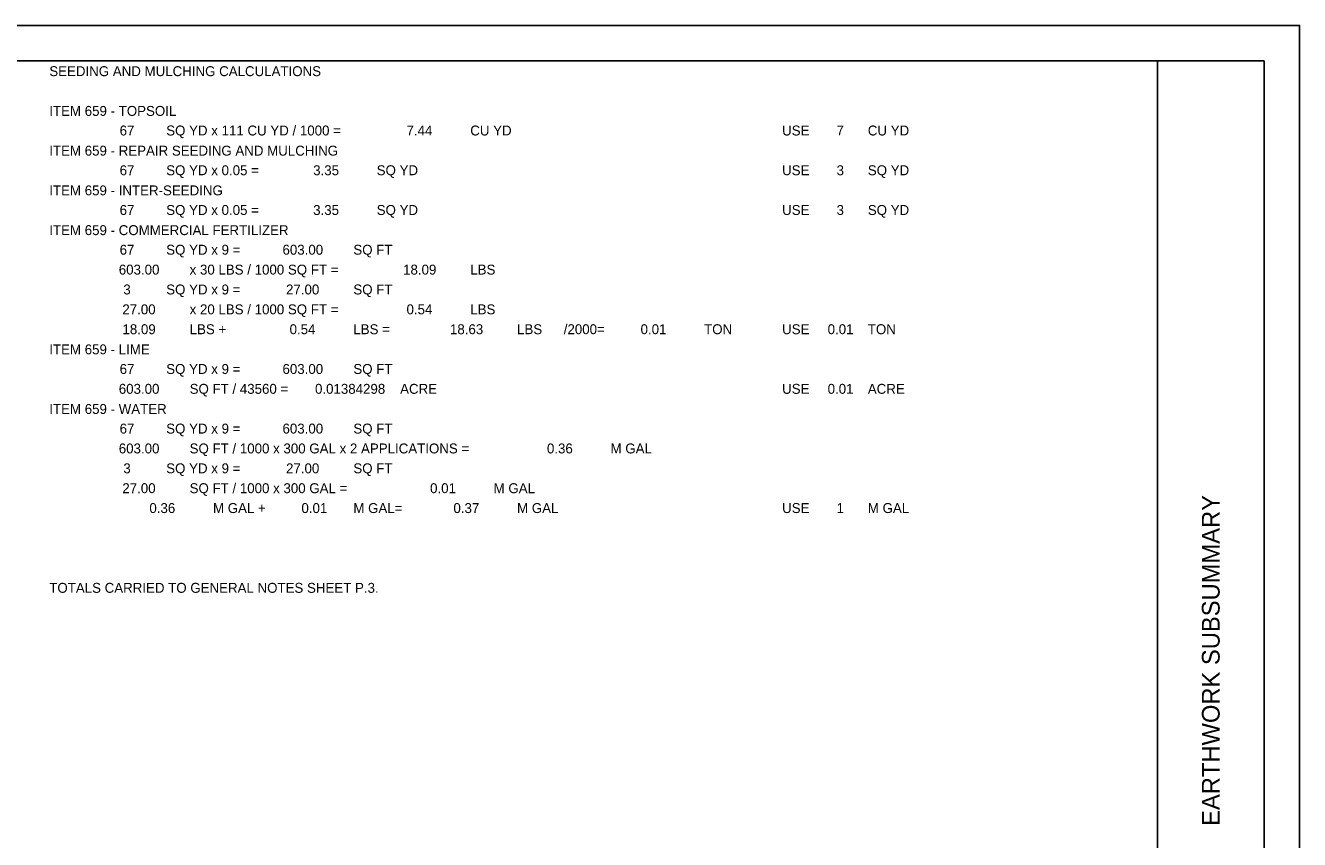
# Model space of a CAD drawing. Extents: x 0 to 34, y 0 to 22.
# Drawn here: x 16.05 to 34, y 10.53 to 22 of the extents above; entities that cross this region are included whole.
import ezdxf

# ---------------------------------------------------------------- set-up
doc = ezdxf.new("R2010")
doc.units = 0
for name, color, linetype in [('SH_Border', 7, 'Continuous'), ('SH_Cut_Line', 7, 'Continuous'), ('SH_Data', 7, 'Continuous'), ('SH_Text', 7, 'Continuous')]:
    doc.layers.add(name, color=color, linetype=linetype)

msp = doc.modelspace()

# ---------------------------------------------------------------- linework, layer by layer
at = {"layer": 'SH_Border'}
msp.add_line((32, 0.5), (32, 21.5), dxfattribs=at)
msp.add_lwpolyline([(1.5, 21.5), (33.5, 21.5), (33.5, 0.5), (1.5, 0.5)], close=True, dxfattribs=at)
at = {"layer": 'SH_Cut_Line'}
msp.add_lwpolyline([(0, 0), (34, 0), (34, 22), (0, 22)], close=True, dxfattribs=at)

# ---------------------------------------------------------------- texts
at = {"layer": 'SH_Data'}
msp.add_text('EARTHWORK SUBSUMMARY', height=0.25, rotation=90, dxfattribs=at).set_placement((32.875, 10.722))
at = {"layer": 'SH_Text'}
for s, p in [('SEEDING AND MULCHING CALCULATIONS', (16.389, 21.286)), ('ITEM 659 - TOPSOIL', (16.389, 20.726)), ('67', (17.38, 20.45)), ('SQ YD x 111 CU YD / 1000 =', (18.036, 20.45)), ('7.44', (21.421, 20.45)), ('CU YD', (22.319, 20.45)), ('USE', (26.712, 20.45)), ('7', (27.478, 20.45)), ('CU YD', (27.919, 20.45)), ('ITEM 659 - REPAIR SEEDING AND MULCHING', (16.389, 20.166)), ('67', (17.38, 19.89)), ('SQ YD x 0.05 =', (18.036, 19.89)), ('3.35', (20.106, 19.89)), ('SQ YD', (21.001, 19.89)), ('USE', (26.712, 19.89)), ('3', (27.479, 19.89)), ('SQ YD', (27.919, 19.89)), ('ITEM 659 - INTER-SEEDING', (16.389, 19.606)), ('67', (17.38, 19.33)), ('SQ YD x 0.05 =', (18.036, 19.33)), ('3.35', (20.106, 19.33)), ('SQ YD', (21.001, 19.33)), ('USE', (26.712, 19.33)), ('3', (27.479, 19.33)), ('SQ YD', (27.919, 19.33)), ('ITEM 659 - COMMERCIAL FERTILIZER', (16.389, 19.046)), ('67', (17.38, 18.77)), ('SQ YD x 9 =', (18.036, 18.77)), ('603.00', (19.674, 18.77)), ('SQ FT', (20.672, 18.77)), ('603.00', (17.368, 18.49)), ('x 30 LBS / 1000 SQ FT =', (18.366, 18.49)), ('18.09', (21.373, 18.49)), ('LBS', (22.319, 18.49)), ('3', (17.432, 18.21)), ('SQ YD x 9 =', (18.036, 18.21)), ('27.00', (19.724, 18.21)), ('SQ FT', (20.672, 18.21)), ('27.00', (17.418, 17.93)), ('x 20 LBS / 1000 SQ FT =', (18.366, 17.93)), ('0.54', (21.421, 17.93)), ('LBS', (22.319, 17.93)), ('18.09', (17.42, 17.65)), ('LBS +', (18.366, 17.65)), ('0.54', (19.774, 17.65)), ('LBS =', (20.672, 17.65)), ('18.63', (22.033, 17.65)), ('LBS', (22.978, 17.65)), ('/2000=', (23.636, 17.65)), ('0.01', (24.718, 17.65)), ('TON', (25.613, 17.65)), ('USE', (26.712, 17.65)), ('0.01', (27.353, 17.65)), ('TON', (27.919, 17.65)), ('ITEM 659 - LIME', (16.389, 17.366)), ('67', (17.38, 17.09)), ('SQ YD x 9 =', (18.036, 17.09)), ('603.00', (19.674, 17.09)), ('SQ FT', (20.672, 17.09)), ('603.00', (17.368, 16.81)), ('SQ FT / 43560 =', (18.366, 16.81)), ('0.01384298', (20.132, 16.81)), ('ACRE', (21.331, 16.81)), ('USE', (26.712, 16.81)), ('0.01', (27.353, 16.81)), ('ACRE', (27.919, 16.81)), ('ITEM 659 - WATER', (16.389, 16.526)), ('67', (17.38, 16.25)), ('SQ YD x 9 =', (18.036, 16.25)), ('603.00', (19.674, 16.25)), ('SQ FT', (20.672, 16.25)), ('603.00', (17.368, 15.97)), ('SQ FT / 1000 x 300 GAL x 2 APPLICATIONS =', (18.366, 15.97)), ('0.36', (23.399, 15.97)), ('M GAL', (24.295, 15.97)), ('3', (17.432, 15.69)), ('SQ YD x 9 =', (18.036, 15.69)), ('27.00', (19.724, 15.69)), ('SQ FT', (20.672, 15.69)), ('27.00', (17.418, 15.41)), ('SQ FT / 1000 x 300 GAL =', (18.366, 15.41)), ('0.01', (21.753, 15.41)), ('M GAL', (22.648, 15.41)), ('0.36', (17.799, 15.13)), ('M GAL +', (18.695, 15.13)), ('0.01', (19.941, 15.13)), ('M GAL=', (20.672, 15.13)), ('0.37', (22.082, 15.13)), ('M GAL', (22.978, 15.13)), ('USE', (26.712, 15.13)), ('1', (27.479, 15.13)), ('M GAL', (27.919, 15.13)), ('TOTALS CARRIED TO GENERAL NOTES SHEET P.3.', (16.389, 14.006))]:
    msp.add_text(s, height=0.14, dxfattribs=at).set_placement(p)

doc.saveas('drawing.dxf')
